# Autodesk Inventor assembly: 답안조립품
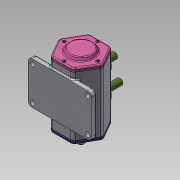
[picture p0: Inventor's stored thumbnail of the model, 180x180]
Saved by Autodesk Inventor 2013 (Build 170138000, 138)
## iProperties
Created: 2021-06
Part Number: 답안조립품
Document SubType Name: Assembly
Designer: Administrator
Author: Administrator
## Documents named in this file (11)
- C:\Documents and Settings\Administrator\바탕 화면\710606V1026\답안조립품.iam
- C:\Documents and Settings\Administrator\바탕 화면\710606V1026\본체.ipt
- C:\Documents and Settings\Administrator\바탕 화면\710606V1026\앞커버.ipt
- C:\Documents and Settings\Administrator\바탕 화면\710606V1026\뒷커버.ipt
- C:\Documents and Settings\Administrator\바탕 화면\710606V1026\부시.ipt
- C:\Documents and Settings\Administrator\바탕 화면\710606V1026\오일실.ipt
- C:\Documents and Settings\Administrator\바탕 화면\710606V1026\베어링 6203.ipt
- C:\Documents and Settings\Administrator\바탕 화면\710606V1026\편심축.ipt
- C:\Documents and Settings\Administrator\바탕 화면\710606V1026\베어링 6302.ipt
- C:\Documents and Settings\Administrator\바탕 화면\710606V1026\슬라이더.ipt
- C:\Documents and Settings\Administrator\바탕 화면\710606V1026\볼트 M4.ipt
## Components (10 placed, 3 different names)
1. 8-오일실:1
2. 7-베어링 6203:1
3. 9-M4-소켓머리:1
4. 9-M4-소켓머리:2
5. 9-M4-소켓머리:3
6. 9-M4-소켓머리:4
7. 9-M4-소켓머리:5
8. 9-M4-소켓머리:6
9. 9-M4-소켓머리:7
10. 9-M4-소켓머리:8
